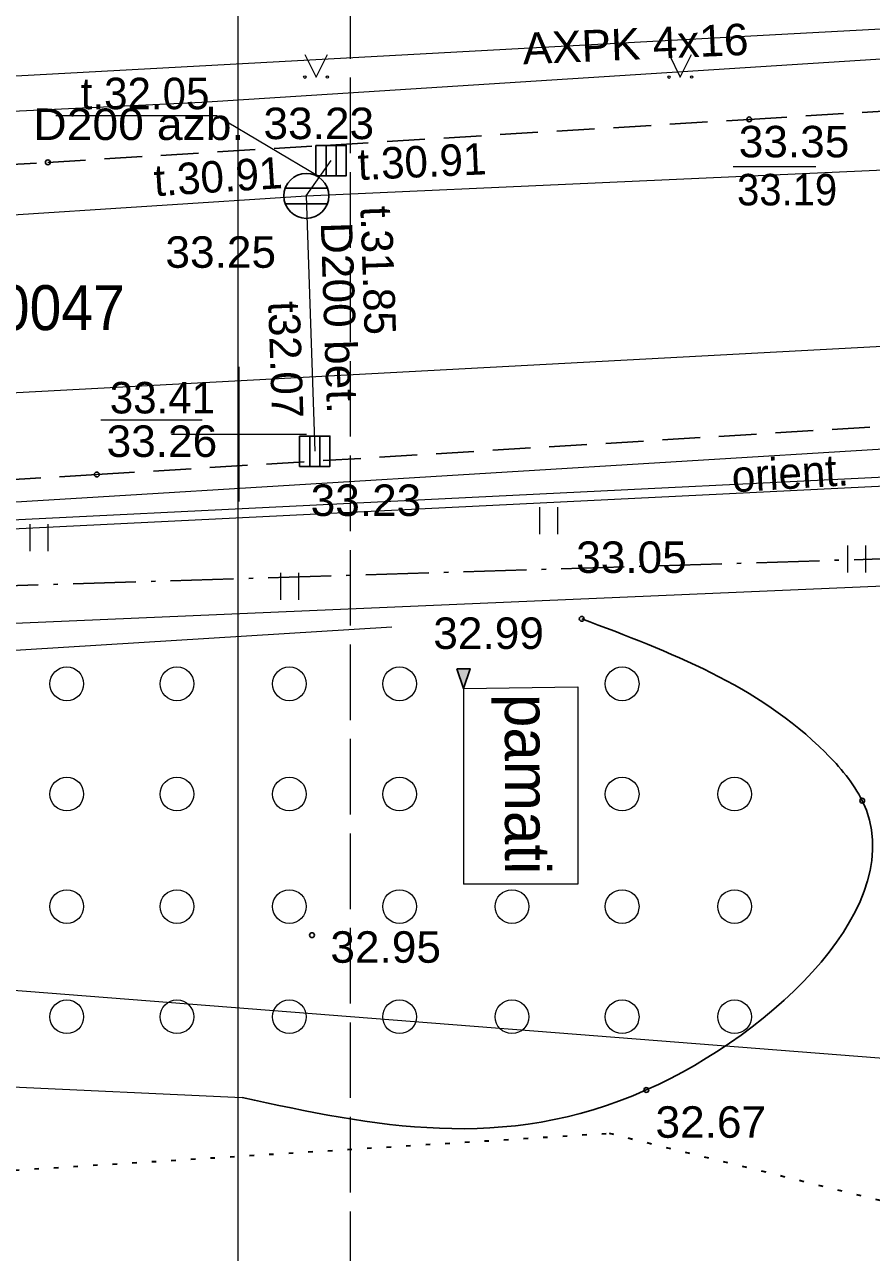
# Model space of a CAD drawing. Extents: x 380758 to 381729, y 283236 to 283533.
# Drawn here: x 381345.23 to 381364.07, y 283331.81 to 283359.1 of the extents above; entities that cross this region are included whole.
import ezdxf
from ezdxf.enums import TextEntityAlignment as Align

# ---------------------------------------------------------------- set-up
doc = ezdxf.new("R2010")
doc.units = 0
doc.header["$LTSCALE"] = 0.28
for name, pattern in [('DOT_DASHED', [7.7, 5, -1.2, 0.3, -1.2]), ('DOTTED', [1.5, 0.3, -1.2]), ('LONG_DASHED', [7.5, 6, -1.5]), ('MEDIUM_DASHED', [4.5, 3, -1.5])]:
    doc.linetypes.add(name, pattern=pattern)
for name, color, linetype, lineweight in [('1', 7, 'Continuous', 13), ('11', 7, 'Continuous', 13), ('17', 7, 'Continuous', 13), ('21', 7, 'Continuous', 25), ('23', 7, 'Continuous', 13), ('25', 7, 'DOTTED', 35), ('29', 7, 'DOT_DASHED', 25), ('30', 7, 'Continuous', 13), ('35', 7, 'Continuous', 13), ('37', 7, 'MEDIUM_DASHED', 13), ('4', 7, 'Continuous', 13), ('42', 7, 'Continuous', 13), ('45', 7, 'Continuous', 13), ('47', 7, 'Continuous', 13), ('48', 7, 'Continuous', 25), ('58', 7, 'Continuous', 25), ('63', 7, 'Continuous', 13), ('7', 7, 'Continuous', 13), ('9', 7, 'Continuous', 13)]:
    doc.layers.add(name, color=color, linetype=linetype, lineweight=lineweight)
doc.layers.add('59', color=7, linetype='Continuous')

msp = doc.modelspace()

# ---------------------------------------------------------------- hatches: boundary and pattern name
at = {"layer": '58'}
msp.add_hatch(color=256, dxfattribs=at).paths.add_polyline_path([(381354.842, 283344.783), (381355.142, 283344.783), (381354.992, 283344.35)])

# ---------------------------------------------------------------- linework, layer by layer
at = {"layer": '1'}
msp.add_lwpolyline([(381332.011, 283346.611), (381337.939, 283345.494), (381380.547, 283347.324)], dxfattribs=at)
at = {"layer": '11'}
for p, q in [((381351.498, 283355.296), (381395.567, 283357.283)), ((381351.498, 283355.296), (381352.049, 283356.08)), ((381303.438, 283352.216), (381351.498, 283355.296)), ((381351.498, 283355.296), (381351.687, 283349.619))]:
    msp.add_line(p, q, dxfattribs=at)
msp.add_lwpolyline([(381345.925, 283357.086), (381349.502, 283357.086), (381351.795, 283355.719)], dxfattribs=at)
at = {"layer": '17'}
msp.add_lwpolyline([(381328.435, 283347.489), (381346.869, 283348.605), (381368.701, 283349.94), (381389.117, 283351.081)], dxfattribs=at)
at = {"layer": '21'}
msp.add_spline([(381357.622, 283345.895), (381363.036, 283342.929), (381363.86, 283341.854), (381359.059, 283335.423), (381350.071, 283335.255)], degree=3, dxfattribs=at)
at = {"layer": '23'}
for p, q in [((381356.691, 283347.779), (381356.691, 283348.379)), ((381357.091, 283347.779), (381357.091, 283348.379)), ((381345.36, 283347.401), (381345.36, 283348.001)), ((381345.76, 283347.401), (381345.76, 283348.001)), ((381363.537, 283346.929), (381363.537, 283347.529)), ((381363.937, 283346.929), (381363.937, 283347.529)), ((381350.931, 283346.315), (381350.931, 283346.915)), ((381351.331, 283346.315), (381351.331, 283346.915))]:
    msp.add_line(p, q, dxfattribs=at)
for points in [[(381351.467, 283358.437), (381351.717, 283357.937), (381351.967, 283358.437)], [(381359.565, 283358.437), (381359.815, 283357.937), (381360.065, 283358.437)]]:
    msp.add_lwpolyline(points, dxfattribs=at)
for centre, radius in [((381351.4668, 283357.9367), 0.028), ((381351.9668, 283357.9367), 0.0263), ((381359.5648, 283357.9367), 0.028), ((381360.0648, 283357.9367), 0.0263), ((381346.1713, 283344.4503), 0.375), ((381348.6213, 283344.4503), 0.375), ((381351.1213, 283344.4503), 0.375), ((381353.5713, 283344.4503), 0.375), ((381358.5213, 283344.4503), 0.375), ((381346.1713, 283342.0003), 0.375), ((381348.6213, 283342.0003), 0.375), ((381351.1213, 283342.0003), 0.375), ((381353.5713, 283342.0003), 0.375), ((381358.5213, 283342.0003), 0.375), ((381361.0213, 283342.0003), 0.375), ((381346.1713, 283339.5003), 0.375), ((381348.6213, 283339.5003), 0.375), ((381351.1213, 283339.5003), 0.375), ((381353.5713, 283339.5003), 0.375), ((381356.0713, 283339.5003), 0.375), ((381358.5213, 283339.5003), 0.375), ((381361.0213, 283339.5003), 0.375), ((381346.1713, 283337.0503), 0.375), ((381348.6213, 283337.0503), 0.375), ((381351.1213, 283337.0503), 0.375), ((381353.5713, 283337.0503), 0.375), ((381356.0713, 283337.0503), 0.375), ((381358.5213, 283337.0503), 0.375), ((381361.0213, 283337.0503), 0.375)]:
    msp.add_circle(centre, radius, dxfattribs=at)
at = {"layer": '25'}
msp.add_lwpolyline([(380965.254, 283306.611), (380999.033, 283308.647), (381050.794, 283310.677), (381081.859, 283313.257), (381112.788, 283315.836), (381135.685, 283318.987), (381169.311, 283321.878), (381185.52, 283321.507), (381211.031, 283321.569), (381227.246, 283323.167), (381243.045, 283326.858), (381256.971, 283328.14), (381276.827, 283329.124), (381289.49, 283330.785), (381296.806, 283333.369), (381324.562, 283332.372), (381358.23, 283334.462), (381389.309, 283326.777)], dxfattribs=at)
at = {"layer": '29'}
msp.add_lwpolyline([(381382.445, 283347.789), (381323.739, 283345.976), (381318.681, 283344.254), (381314.371, 283340.635), (381307.869, 283332.233)], dxfattribs=at)
at = {"layer": '30'}
for points in [[(381350, 283351.5), (381350, 283350), (381350, 283348.5)], [(381348.5, 283350), (381350, 283350), (381351.5, 283350)]]:
    msp.add_lwpolyline(points, dxfattribs=at)
at = {"layer": '35'}
msp.add_line((381339.015, 283335.77), (381350.071, 283335.255), dxfattribs=at)
msp.add_lwpolyline([(381353.396, 283345.712), (381328.377, 283344.165), (381328.548, 283337.422)], dxfattribs=at)
at = {"layer": '37', "lineweight": 25}
for points in [[(381309.426, 283365.712), (381316.201, 283360.727), (381318.377, 283359.189), (381320.24, 283357.84), (381330.826, 283355.148), (381345.75, 283356.042), (381361.347, 283356.997), (381379.416, 283358.112), (381395.576, 283359.052), (381419.83, 283360.537), (381435.717, 283361.494), (381453.632, 283362.598)], [(381328.405, 283347.988), (381346.839, 283349.104), (381368.671, 283350.439), (381379.766, 283351.087)]]:
    msp.add_lwpolyline(points, dxfattribs=at)
at = {"layer": '42'}
msp.add_line((381354.992, 283344.35), (381354.996, 283339.996), dxfattribs=at)
msp.add_lwpolyline([(381354.992, 283344.35), (381357.534, 283344.382), (381357.538, 283339.998), (381354.996, 283339.996)], dxfattribs=at)
at = {"layer": '45'}
msp.add_lwpolyline([(381330.905, 283356.964), (381332.349, 283356.807), (381338.082, 283356.85), (381349.173, 283357.381), (381370.904, 283358.763), (381391.496, 283360.078)], dxfattribs=at)
at = {"layer": '47'}
msp.add_lwpolyline([(381327.333, 283349.98), (381423.16, 283355.103), (381470.505, 283357.6)], dxfattribs=at)
at = {"layer": '48'}
for p, q in [((381351.936, 283356.418), (381351.936, 283355.743)), ((381352.161, 283356.418), (381352.161, 283355.743)), ((381351.03, 283355.471), (381351.966, 283355.471)), ((381351.03, 283355.121), (381351.966, 283355.121)), ((381351.574, 283349.957), (381351.574, 283349.282)), ((381351.799, 283349.957), (381351.799, 283349.282))]:
    msp.add_line(p, q, dxfattribs=at)
for points in [[(381351.711, 283356.418), (381352.386, 283356.418), (381352.386, 283355.743), (381351.711, 283355.743)], [(381351.349, 283349.957), (381352.024, 283349.957), (381352.024, 283349.282), (381351.349, 283349.282)]]:
    msp.add_lwpolyline(points, close=True, dxfattribs=at)
msp.add_circle((381351.498, 283355.296), 0.5, dxfattribs=at)
at = {"layer": '58', "lineweight": 13}
for p, q in [((381360.993, 283355.95), (381362.829, 283355.95)), ((381346.931, 283350.317), (381349.183, 283350.317))]:
    msp.add_line(p, q, dxfattribs=at)
at = {"layer": '58'}
msp.add_lwpolyline([(381354.842, 283344.783), (381355.142, 283344.783), (381354.992, 283344.35)], close=True, dxfattribs=at)
for centre in [(381361.347, 283356.9971), (381345.75, 283356.0421), (381346.839, 283349.1041), (381357.622, 283345.8951), (381363.86, 283341.8541), (381351.625, 283338.8641), (381359.059, 283335.4231)]:
    msp.add_circle(centre, 0.0534, dxfattribs=at)
at = {"layer": '63', "linetype": 'LONG_DASHED'}
msp.add_line((381352.477, 283259.645), (381352.477, 283469.645), dxfattribs=at)
at = {"layer": '63'}
msp.add_line((381349.977, 283467.145), (381349.977, 283262.145), dxfattribs=at)
at = {"layer": '7'}
for points in [[(381392.891, 283340.196), (381393.772, 283340.688), (381392.676, 283360.539), (381361.658, 283358.859), (381333.586, 283357.337)], [(381322.484, 283345.592), (381325.517, 283346.388), (381330.34, 283347.209), (381341.787, 283347.939), (381366.473, 283349.159), (381379.717, 283349.182)], [(381325.937, 283346.257), (381330.363, 283347.01), (381341.798, 283347.739), (381366.478, 283348.959), (381379.677, 283348.982)]]:
    msp.add_lwpolyline(points, dxfattribs=at)
at = {"layer": '9'}
msp.add_lwpolyline([(381159.963, 283331.675), (381191.524, 283331.747), (381195.757, 283331.812), (381227.539, 283340.262), (381286.928, 283343.391), (381326.31, 283339.103), (381385.472, 283334.479), (381409.418, 283335.25)], dxfattribs=at)

# ---------------------------------------------------------------- texts
at = {"layer": '11'}
msp.add_text('t.32.05', height=0.7, dxfattribs=at).set_placement((381347.9125, 283357.223), align=Align.CENTER)
at = {"layer": '11', "width": 1.1}
msp.add_text('D200 azb.', height=0.7, dxfattribs=at).set_placement((381347.773, 283356.539), align=Align.CENTER)
at = {"layer": '11'}
for s, rotation, p in [('t.30.91', 2.582, (381354.0862, 283355.7125)), ('t.30.91', 3.667, (381349.5566, 283355.379)), ('t.31.85', 271.907, (381352.7481, 283353.6281)), ('t32.07', 271.907, (381350.6929, 283351.6436))]:
    msp.add_text(s, height=0.7, rotation=rotation, dxfattribs=at).set_placement(p, align=Align.CENTER)
at = {"layer": '11', "width": 1.05}
msp.add_text('D200 bet.', height=0.7, rotation=271.907, dxfattribs=at).set_placement((381351.8888, 283352.5741), align=Align.CENTER)
at = {"layer": '17'}
msp.add_text('orient.', height=0.7, rotation=3.499, dxfattribs=at).set_placement((381362.2771, 283348.7859), align=Align.CENTER)
at = {"layer": '4'}
msp.add_text('pamati', height=1, rotation=270.053, dxfattribs=at).set_placement((381355.914, 283344.226))
at = {"layer": '45', "width": 1.05}
msp.add_text('AXPK 4x16', height=0.7, rotation=2.412, dxfattribs=at).set_placement((381356.321, 283358.221))
at = {"layer": '48', "width": 1.05}
for s, p in [('33.23', (381350.545, 283356.558)), ('33.25', (381348.365, 283353.698)), ('33.23', (381351.595, 283348.182))]:
    msp.add_text(s, height=0.7, dxfattribs=at).set_placement(p)
at = {"layer": '58'}
for s, width, p in [('33.35', 1.05, (381361.114, 283356.153)), ('33.19', 0.95, (381361.077, 283355.085)), ('33.26', 1.05, (381347.057, 283349.494)), ('33.05', 1.05, (381357.499, 283346.916)), ('32.99', 1.05, (381354.322, 283345.226)), ('32.95', 1.05, (381352.033, 283338.251)), ('32.67', 1.05, (381359.263, 283334.361))]:
    msp.add_text(s, height=0.7, dxfattribs=dict(at, width=width)).set_placement(p)
msp.add_text('33.41', height=0.7, dxfattribs=at).set_placement((381347.127, 283350.461))
at = {"layer": '59', "width": 0.95}
msp.add_text('62290120047', height=1, dxfattribs=at).set_placement((381339.692, 283352.312))

doc.saveas('drawing.dxf')
